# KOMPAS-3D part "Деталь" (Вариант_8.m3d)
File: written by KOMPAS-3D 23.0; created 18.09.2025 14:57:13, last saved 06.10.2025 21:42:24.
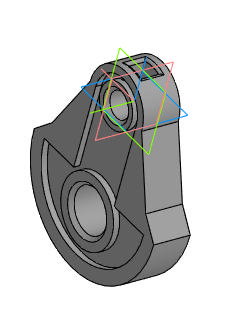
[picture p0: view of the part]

Document properties: Автор: ssafo; Полное имя файла: C:\Users\ssafo\OneDrive\Desktop\ЦД_Грант\Решенные варианты\Вариант_8.m3d

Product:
- Part/product: Деталь
    Масса: 2.465117
    Форматы листов документа: A4

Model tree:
1. Эскиз:1
2. Элемент выдавливания:1
     Расстояние 1 = 15; Расстояние 2 = 15
3. Эскиз:2  (with: Элемент выдавливания:1)
4. Элемент выдавливания:2
     Расстояние 2 = 5
5. Эскиз:12
6. Элемент выдавливания:10
     Расстояние 1 = 28
7. Скругление:1  (with: Элемент выдавливания:10)
     Радиус = 2
8. Эскиз:13  (with: Элемент выдавливания:2)
9. Элемент выдавливания:11
     Расстояние 1 = 5
10. Эскиз:14  (with: Элемент выдавливания:2)
11. Элемент выдавливания:12
     Расстояние 1 = 5
12. Эскиз:15  (with: Элемент выдавливания:11)
13. Элемент выдавливания:13
     Расстояние 2 = 30
14. Эскиз:16  (with: Элемент выдавливания:12)
15. Элемент выдавливания:14
     Расстояние 2 = 30
16. Зеркальный массив:1
17. Экземпляр ( 1 )
18. Экземпляр ( 2 )  (with: Элемент выдавливания:2, Элемент выдавливания:14, Элемент выдавливания:12, Элемент выдавливания:13, Элемент выдавливания:11)
19. Фаска:1  (with: Элемент выдавливания:12, Элемент выдавливания:11, Элемент выдавливания:14, Элемент выдавливания:13)
     Угол = 45; Длина 1 = 3; Длина 2 = 3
